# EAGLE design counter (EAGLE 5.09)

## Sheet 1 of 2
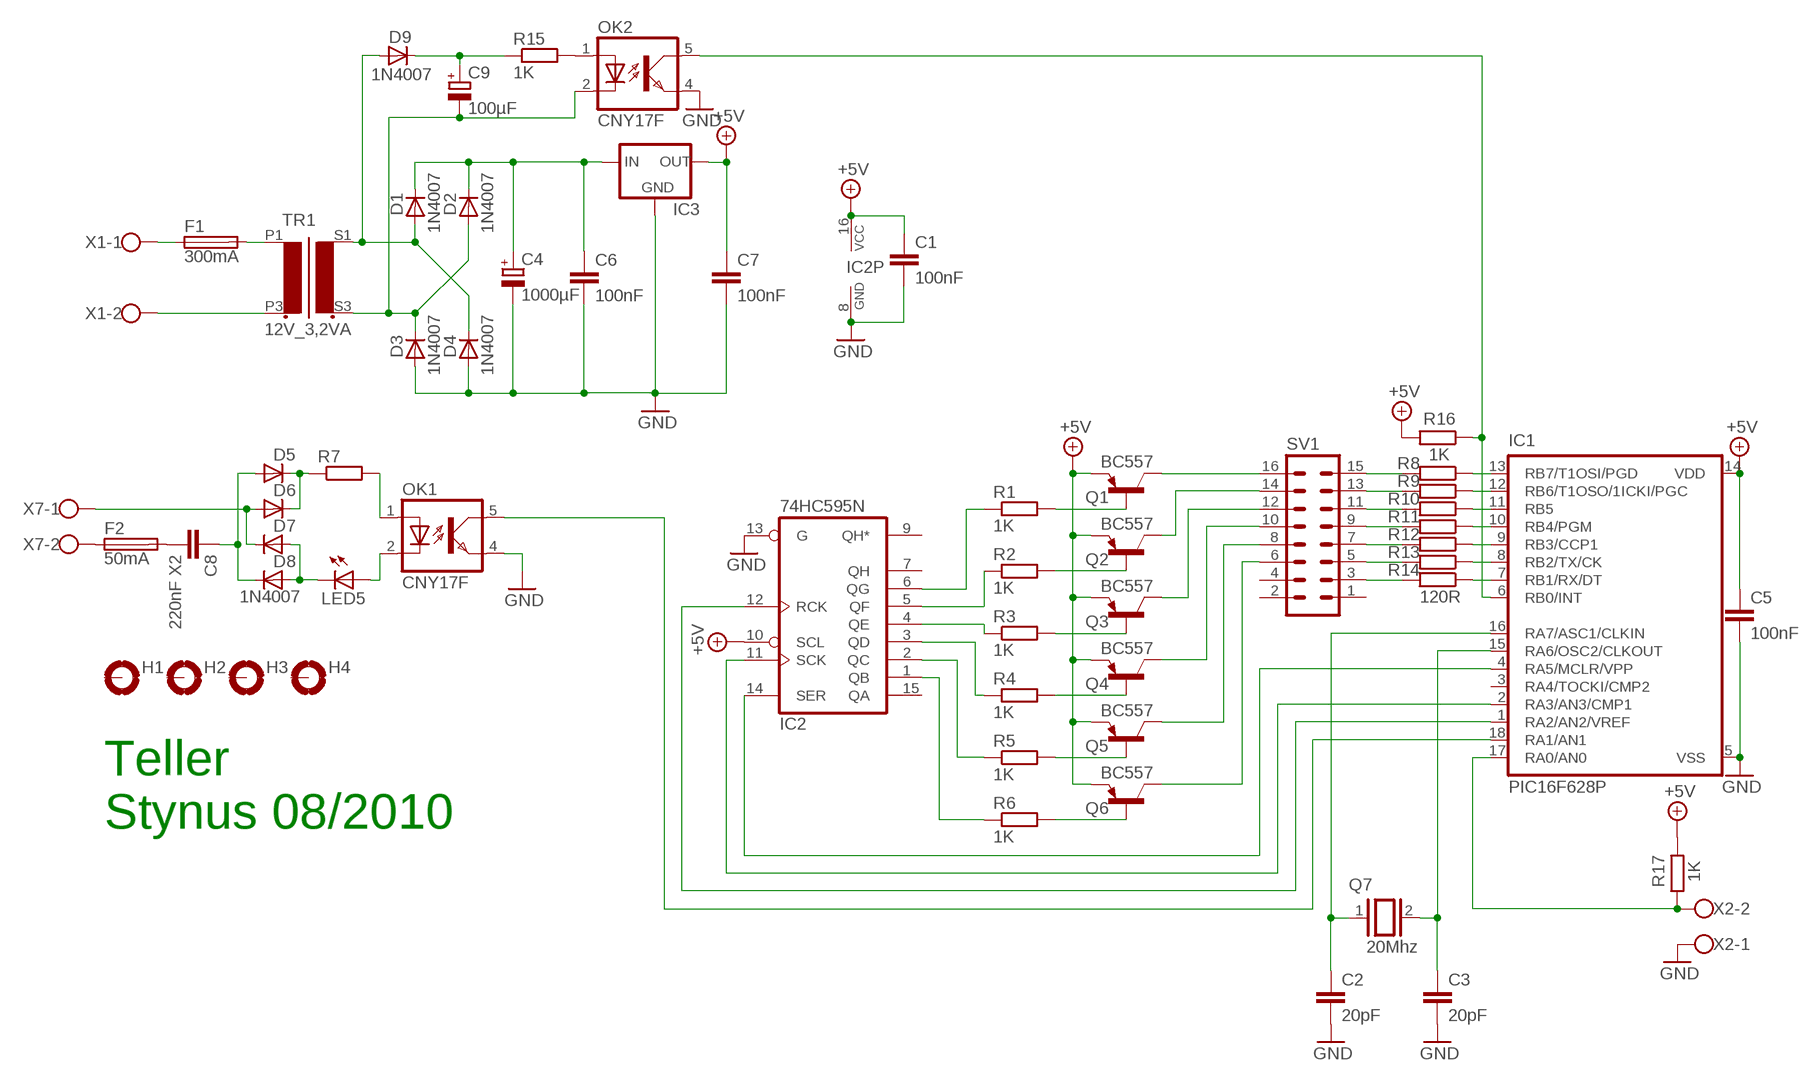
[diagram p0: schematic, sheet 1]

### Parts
C1  100nF  C-EU050-025X075  [C050-025X075]
C2  20pF  C-EU050-025X075  [C050-025X075]
C3  20pF  C-EU050-025X075  [C050-025X075]
C4  1000µF  CPOL-EUE5-13  [E5-13]
C5  100nF  C-EU050-025X075  [C050-025X075]
C6  100nF  C-EU050-025X075  [C050-025X075]
C7  100nF  C-EU050-025X075  [C050-025X075]
C8  220nF X2  C-EU150-091X182  [C150-091X182]
C9  100µF  CPOL-EUE5-10.5  [E5-10,5]
D1  1N4007  1N4004  [DO41-10]
D2  1N4007  1N4004  [DO41-10]
D3  1N4007  1N4004  [DO41-10]
D4  1N4007  1N4004  [DO41-10]
D5  1N4007  1N4004  [DO41-10]
D6  1N4007  1N4004  [DO41-10]
D7  1N4007  1N4004  [DO41-10]
D8  1N4007  1N4004  [DO41-10]
D9  1N4007  1N4004  [DO41-10]
F1  300mA  FUSESH22,5A  [SH22,5A]
F2  50mA  FUSESH22,5A  [SH22,5A]
H1  MOUNT-PAD-ROUND3.0  [3,0-PAD]
H2  MOUNT-PAD-ROUND3.0  [3,0-PAD]
H3  MOUNT-PAD-ROUND3.0  [3,0-PAD]
H4  MOUNT-PAD-ROUND3.0  [3,0-PAD]
IC1  PIC16F628P  [DIL18]
IC2  74HC595N  [DIL16]
IC3  78XXS  [78XXS]
LED5  LED5MM  [LED5MM]
OK1  CNY17F  [DIL06]
OK2  CNY17F  [DIL06]
Q1  BC557  BC557A  [TO92-EBC]
Q2  BC557  BC557A  [TO92-EBC]
Q3  BC557  BC557A  [TO92-EBC]
Q4  BC557  BC557A  [TO92-EBC]
Q5  BC557  BC557A  [TO92-EBC]
Q6  BC557  BC557A  [TO92-EBC]
Q7  20Mhz  XTAL/S  [QS]
R1  1K  R-EU_0204/7  [0204/7]
R2  1K  R-EU_0204/7  [0204/7]
R3  1K  R-EU_0204/7  [0204/7]
R4  1K  R-EU_0204/7  [0204/7]
R5  1K  R-EU_0204/7  [0204/7]
R6  1K  R-EU_0204/7  [0204/7]
R7  R-EU_0207/10  [0207/10]
R8  R-EU_0207/10  [0207/10]
R9  R-EU_0207/10  [0207/10]
R10  R-EU_0207/10  [0207/10]
R11  R-EU_0207/10  [0207/10]
R12  R-EU_0207/10  [0207/10]
R13  R-EU_0207/10  [0207/10]
R14  120R  R-EU_0207/10  [0207/10]
R15  1K  R-EU_0204/7  [0204/7]
R16  1K  R-EU_0207/10  [0207/10]
R17  1K  R-EU_0207/10  [0207/10]
SV1  MA08-2  [MA08-2]
TR1  12V_3,2VA  2V_3,2VA  [12V_3,2VA]
X1  W237-02P  [W237-132]
X2  W237-02P  [W237-132]
X7  W237-02P  [W237-132]

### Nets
+5V: C1.1 C5.1 C7.1 IC1.14(VDD) IC2.10(SCL) IC2.16(VCC) IC3.OUT Q1.E Q2.E Q3.E Q4.E Q5.E Q6.E R16.2 R17.1
GND: C1.2 C2.2 C3.2 C4.- C5.2 C6.2 C7.2 D3.A D4.A IC1.5(VSS) IC2.8(GND) IC2.13(G) IC3.GND OK1.4(EMIT) OK2.4(EMIT) X2.1
N$1: Q1.C SV1.16
N$2: Q2.C SV1.14
N$3: Q3.C SV1.12
N$4: Q4.C SV1.10
N$5: R8.2 SV1.15
N$6: R9.2 SV1.13
N$7: R10.2 SV1.11
N$8: Q5.C SV1.8
N$9: Q6.C SV1.6
N$10: Q1.B R1.2
N$11: Q2.B R2.2
N$12: Q3.B R3.2
N$13: Q4.B R4.2
N$14: IC1.13(RB7/T1OSI/PGD) R8.1
N$15: Q5.B R5.2
N$16: IC1.12(RB6/T1OSO/1ICKI/PGC) R9.1
N$17: Q6.B R6.2
N$18: IC2.6(QG) R1.1
N$19: IC2.5(QF) R2.1
N$20: IC1.11(RB5) R10.1
N$21: IC2.4(QE) R3.1
N$22: R11.2 SV1.9
N$23: IC1.10(RB4/PGM) R11.1
N$24: IC2.3(QD) R4.1
N$25: IC2.2(QC) R5.1
N$26: IC1.9(RB3/CCP1) R12.1
N$27: IC1.8(RB2/TX/CK) R13.1
N$28: R12.2 SV1.7
N$29: IC1.7(RB1/RX/DT) R14.1
N$30: C8.2 F2.2
N$31: R13.2 SV1.5
N$32: R14.2 SV1.3
N$33: D6.A D7.C X7.1
N$34: IC2.1(QB) R6.1
N$35: IC1.4(RA5/MCLR/VPP) IC2.14(SER)
N$36: IC1.2(RA3/AN3/CMP1) IC2.11(SCK)
N$37: IC1.1(RA2/AN2/VREF) IC2.12(RCK)
N$38: C3.1 IC1.15(RA6/OSC2/CLKOUT) Q7.2
N$39: C2.1 IC1.16(RA7/ASC1/CLKIN) Q7.1
N$40: D1.A D4.C D9.A TR1.S1
N$41: C9.- D2.A D3.C OK2.2(C) TR1.S3
N$42: C8.1 D5.A D8.C
N$43: F1.1 X1.1
N$44: TR1.P3 X1.2
N$45: F1.2 TR1.P1
N$46: C9.+ D9.C R15.1
N$47: D5.C D6.C R7.1
N$48: D7.A D8.A LED5.K(C)
N$49: OK1.1(A) R7.2
N$50: IC1.18(RA1/AN1) OK1.5(COL)
N$51: LED5.A OK1.2(C)
N$52: C4.+ C6.1 D1.C D2.C IC3.IN
N$53: OK2.1(A) R15.2
N$54: IC1.6(RB0/INT) OK2.5(COL) R16.1
N$55: IC1.17(RA0/AN0) R17.2 X2.2
N$56: F2.1 X7.2
Unconnected: H1.B3,0(MOUNT) H2.B3,0(MOUNT) H3.B3,0(MOUNT) H4.B3,0(MOUNT) IC1.3(RA4/TOCKI/CMP2) IC2.7(QH) IC2.9(QH*) IC2.15(QA) SV1.1 SV1.2 SV1.4

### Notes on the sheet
- Teller
- Stynus 08/2010

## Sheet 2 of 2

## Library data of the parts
C1-C3 C5-C8 = rcl:C-EU: CAPACITOR, European symbol
C4 C9 = rcl:CPOL-EU: POLARIZED CAPACITOR, European symbol
D1-D9 = diode:1N4004: DIODE
F1 F2 = fuse:FUSE: Fuse
H1-H4 = holes:MOUNT-PAD-ROUND: MOUNTING PAD, round
IC1 = microchip:PIC16*F62: FLASH-Based 8-Bit CMOS Microcontroller Source: http://ww1.microchip.com/downloads/en/DeviceDoc/40300C.pdf
IC2 = 74xx-eu:74*595: 8-bit SHIFT REGISTER, output latch
IC3 = v-reg:78XXS: VOLTAGE REGULATOR
LED5 = led:LED: LED
OK1 OK2 = optocoupler:CNY17F: SIEMENS OPTO COUPLER
Q1-Q6 = transistor-pnp:BC557*: PNP Transistror
Q7 = special:XTAL/S: CRYSTAL
R1-R17 = rcl:R-EU_: RESISTOR, European symbol
SV1 = con-lstb:MA08-2: PIN HEADER
TR1 = transfo_12V_3_2VA_Erea:2V_3,2VA
X1 X2 X7 = con-wago-508:W237-02P: WAGO SREW CLAMP

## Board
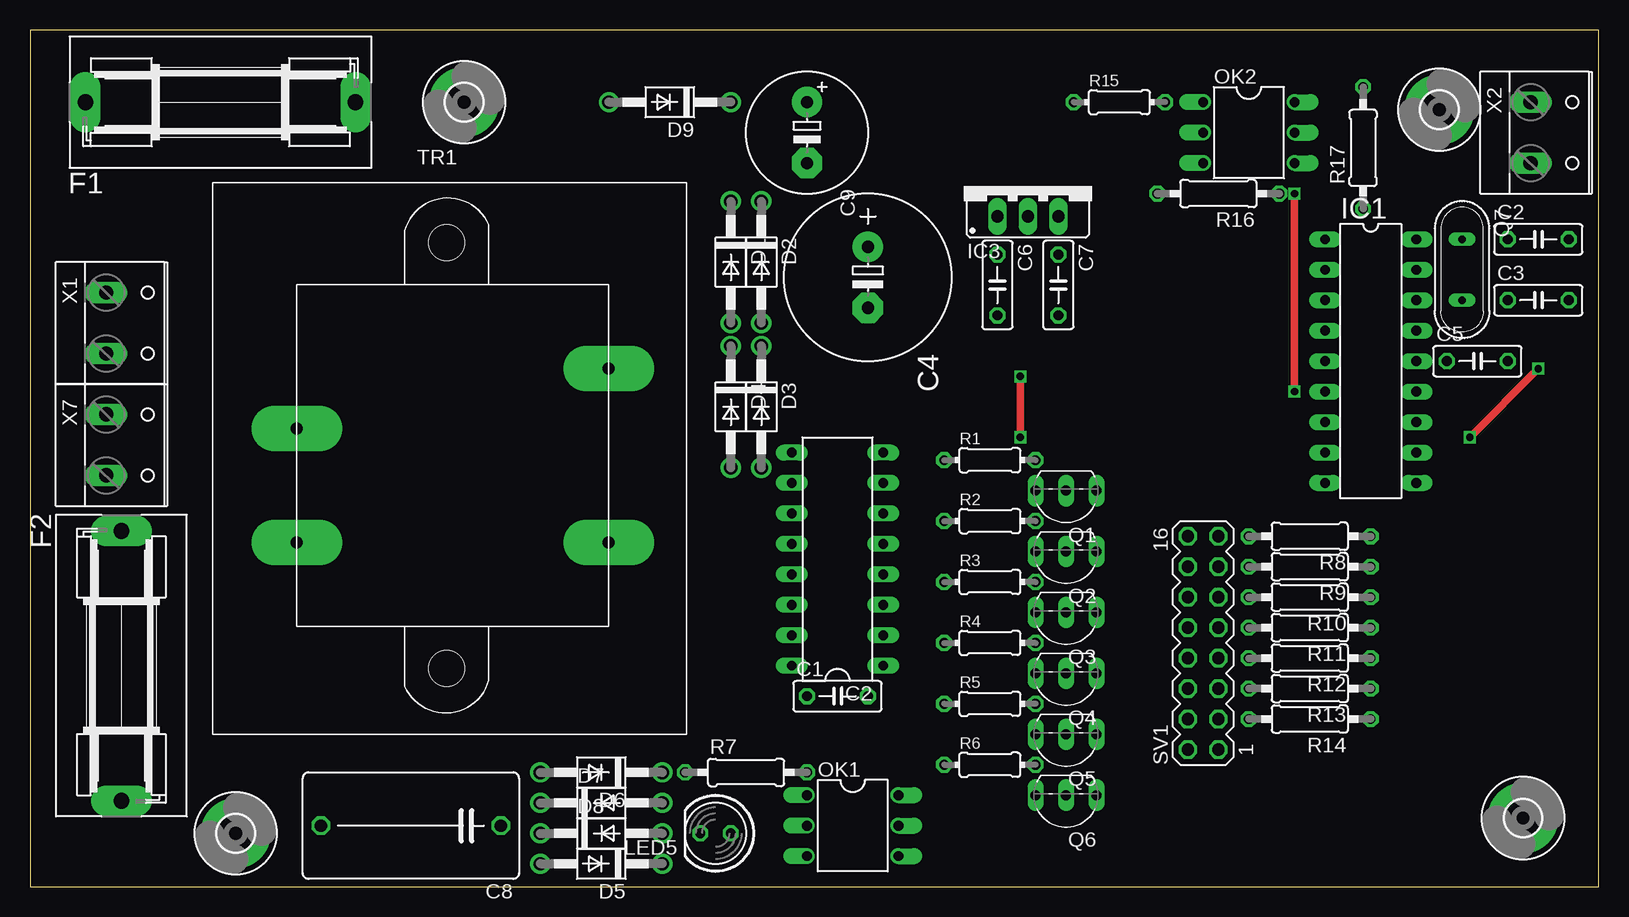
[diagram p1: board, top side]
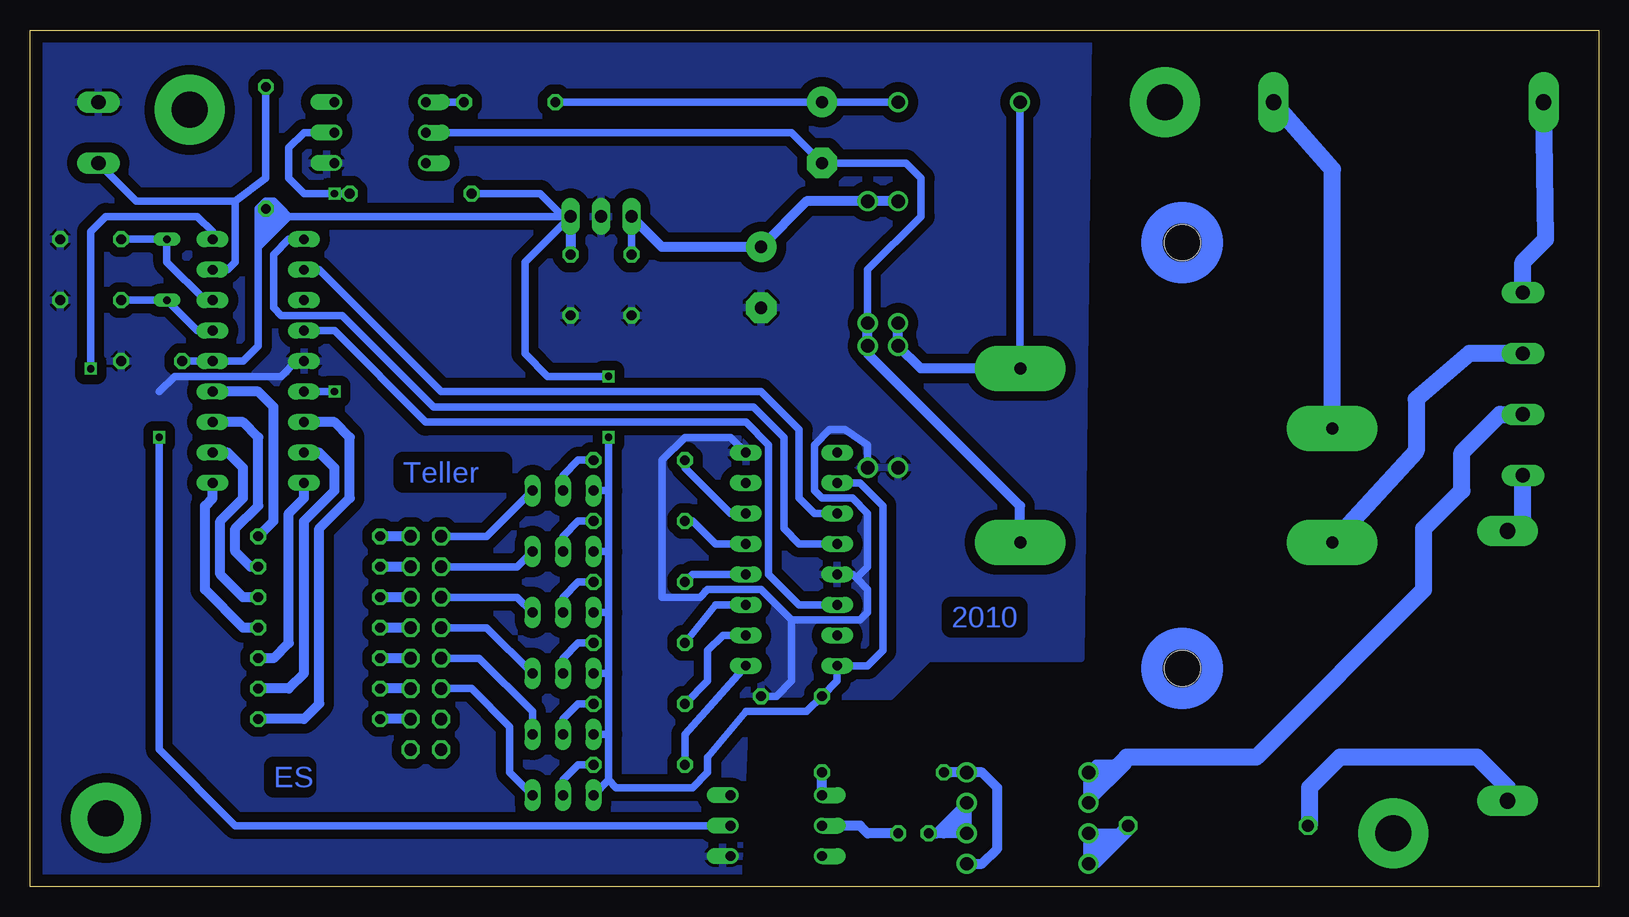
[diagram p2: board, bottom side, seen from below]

Size 130.79 x 71.42 mm. Coordinates in mm from the lower left corner, seen from the top.
Outline: 0,0 130.79,0 130.79,71.42 0,71.42 0,0
Copper layers (1*16): Top 0.035mm / dielectric 1.5mm / Bottom 0.035mm
Design rules "default": minimum track width 10mil, minimum drill 24mil, track to track 8mil, track to pad 8mil, pad to pad 8mil, via to via 8mil, smd to smd 8mil, copper to edge 40mil, drill to drill 8mil, minimum pad ring 10mil, minimum via ring 8mil, stop-mask expansion 4mil, vias tented up to drill 0mil, thermal gap 10mil

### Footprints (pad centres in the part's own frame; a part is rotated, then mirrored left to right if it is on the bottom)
C050-025X075 = drill 0.813 octagon: 1 -2.54,0; 2 2.54,0
E5-13 = drill 1.016 pad 2.54 round: + -2.54,0 | drill 1.016 pad 2.54 octagon: - 2.54,0
C150-091X182 = drill 1.016 octagon: 1 -7.493,0; 2 7.493,0
E5-10,5 = drill 1.016 pad 2.54 round: + -2.54,0 | drill 1.016 pad 2.54 octagon: - 2.54,0
DO41-10 = drill 1.118 round: A 5.08,0; C -5.08,0
SH22,5A = drill 1.321 pad 2.54 long: 1 -11.252,0; 2 11.252,0
3,0-PAD = drill 3 pad 5.842 round: B3,0 0,0
DIL18 = drill 0.813 long: 1 -10.16,-3.81; 2 -7.62,-3.81; 3 -5.08,-3.81; 4 -2.54,-3.81; 5 0,-3.81; 6 2.54,-3.81; 7 5.08,-3.81; 8 7.62,-3.81; 9 10.16,-3.81; 10 10.16,3.81; 11 7.62,3.81; 12 5.08,3.81; 13 2.54,3.81; 14 0,3.81; 15 -2.54,3.81; 16 -5.08,3.81; 17 -7.62,3.81; 18 -10.16,3.81
DIL16 = drill 0.813 long: 1 -8.89,-3.81; 2 -6.35,-3.81; 3 -3.81,-3.81; 4 -1.27,-3.81; 5 1.27,-3.81; 6 3.81,-3.81; 7 6.35,-3.81; 8 8.89,-3.81; 9 8.89,3.81; 10 6.35,3.81; 11 3.81,3.81; 12 1.27,3.81; 13 -1.27,3.81; 14 -3.81,3.81; 15 -6.35,3.81; 16 -8.89,3.81
78XXS = drill 1.016 long: GND 0,-2.54; IN -2.54,-2.54; OUT 2.54,-2.54
LED5MM = drill 0.813 octagon: A -1.27,0; K 1.27,0
DIL06 = drill 0.813 offset: 1 -2.54,-3.81; 2 0,-3.81; 3 2.54,-3.81; 4 2.54,3.81; 5 0,3.81; 6 -2.54,3.81
TO92-EBC = drill 0.813 long: B 0,-1.27; C -2.54,-1.27; E 2.54,-1.27
QS = drill 0.61 long: 1 -2.54,0; 2 2.54,0
0204/7 = drill 0.813 octagon: 1 -3.81,0; 2 3.81,0
0207/10 = drill 0.813 octagon: 1 -5.08,0; 2 5.08,0
MA08-2 = drill 1.016 octagon: 1 -8.89,-1.27; 2 -8.89,1.27; 3 -6.35,-1.27; 4 -6.35,1.27; 5 -3.81,-1.27; 6 -3.81,1.27; 7 -1.27,-1.27; 8 -1.27,1.27; 9 1.27,-1.27; 10 1.27,1.27; 11 3.81,-1.27; 12 3.81,1.27; 13 6.35,-1.27; 14 6.35,1.27; 15 8.89,-1.27; 16 8.89,1.27
12V_3,2VA = drill 1 pad 3.81 long: P1 7,25.5; P3 7,16; S1 33,30.5; S3 33,16 | hole 3: 19.5,5.5; 19.5,41
W237-132 = drill 1.194 long: 1 -2.54,-0.635; 2 2.54,-0.635

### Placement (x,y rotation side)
C1  67.31,15.88 0 top
C2  125.73,53.98 0 top
C3  125.73,48.9 0 top
C4  69.85,50.8 270 top
C5  120.65,43.81 0 top
C6  80.64,50.16 270 top
C7  85.72,50.16 270 top
C8  31.75,5.08 180 top
C9  64.77,62.87 270 top
D1  58.42,52.07 270 top
D2  60.96,52.07 270 top
D3  60.96,40.01 270 top
D4  58.42,40.01 270 top
D5  47.62,1.91 180 top
D6  47.62,9.53 180 top
D7  47.62,6.99 0 top
D8  47.62,4.45 0 top
D9  53.34,65.41 180 top
F1  15.88,65.41 0 top
F2  7.62,18.41 270 top
H1  17.14,4.45 0 top
H2  36.2,65.41 0 top
H3  124.46,5.71 0 top
H4  117.47,64.77 0 top
IC1  111.76,43.81 270 top
IC2  67.31,27.3 90 top
IC3  83.19,58.42 0 top
LED5  57.15,4.45 180 top
OK1  68.58,5.08 270 top
OK2  101.6,62.87 270 top
Q1  86.36,31.75 180 top
Q2  86.36,26.67 180 top
Q3  86.36,21.59 180 top
Q4  86.36,16.51 180 top
Q5  86.36,11.43 180 top
Q6  86.36,6.35 180 top
Q7  119.38,51.44 270 top
R1  80.01,35.56 0 top
R2  80.01,30.48 0 top
R3  80.01,25.4 0 top
R4  80.01,20.32 0 top
R5  80.01,15.24 0 top
R6  80.01,10.16 0 top
R7  59.69,9.53 0 top
R8  106.68,29.21 180 top
R9  106.68,26.67 180 top
R10  106.68,24.13 180 top
R11  106.68,21.59 180 top
R12  106.68,19.05 180 top
R13  106.68,16.51 180 top
R14  106.68,13.97 180 top
R15  90.81,65.41 0 top
R16  99.06,57.78 180 top
R17  111.12,61.59 90 top
SV1  97.79,20.32 90 top
TR1  15.24,12.7 0 top
X1  6.99,46.99 270 top
X2  125.73,62.87 270 top
X7  6.99,36.83 270 top

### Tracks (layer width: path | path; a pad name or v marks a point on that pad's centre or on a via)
+5V  (via drill 0.6)
  Top 0.61: v82.55,37.47 v82.55,42.55
  Bottom 0.61: IC2.10 61.59,33.66 59.69,31.75 59.69,19.68 60.96,18.41 IC2.16 63.5,17.14 C1.1 66.04,14.61 71.12,14.61 74.3,10.79 74.3,9.53 75.56,8.26 81.92,8.26 82.55,8.89 | 82.55,8.89 Q6.E | 82.55,8.89 82.55,12.7 | 82.55,12.7 82.55,17.78 | 82.55,17.78 82.55,22.86 | 82.55,22.86 82.55,27.94 | 82.55,27.94 82.55,33.02 | 82.55,27.94 Q2.E | 82.55,22.86 Q3.E | 82.55,17.78 Q4.E | 82.55,12.7 Q5.E | C5.1 IC1.14 113.03,43.81 111.76,45.09 111.76,53.34 | 109.22,55.88 111.76,53.34 | 85.72,55.24 86.36,55.88 | 82.55,33.02 Q1.E | 82.55,33.02 v82.55,37.47 | v82.55,42.55 87.63,42.55 89.53,44.45 89.53,52.07 IC3.OUT | R16.2 88.27,57.78 86.36,55.88 | 109.86,56.52 110.49,56.52 | 110.49,56.52 R17.1 111.76,55.88 | 109.22,55.88 109.86,56.52 | 111.76,55.88 111.76,55.24 | 111.76,53.98 111.76,54.61 | 111.76,53.34 111.76,53.98 | 111.76,53.98 109.86,55.88 110.49,56.52 | 110.49,56.52 110.49,55.88 111.76,54.61 | 111.76,54.61 111.76,55.24 | 111.76,55.24 111.12,55.88 | 86.36,55.88 109.22,55.88 | 109.86,56.52 110.49,57.15 111.12,57.15 111.76,56.52 111.76,55.88
  Bottom 0.813: C7.1 85.72,55.24 IC3.OUT
GND
  Bottom 0.61: IC2.8 72.39,37.47 76.2,37.47 78.11,35.56 78.11,24.13 74.93,24.13 74.3,24.77 69.85,24.77 67.31,22.23 | 67.31,22.23 61.59,22.23 60.96,22.86 60.96,24.77 61.91,25.72 | 61.91,25.72 62.23,26.04 IC2.13 | IC1.5 108.58,43.81 109.86,42.55 118.75,42.55 120.02,41.27 | C1.2 68.58,15.88 67.31,17.14 67.31,22.23 | D3.A 60.96,36.83 62.87,38.1 64.14,38.1 65.41,36.83 65.41,33.02 64.77,32.38 62.23,32.38 60.96,31.11 60.96,26.67 61.91,25.72
  pour Bottom (isolate 0.813): 43.18,19.05 55.88,19.05 59.05,15.88 71.12,15.88 71.75,0 130.18,0 130.18,71.12 42.55,71.12
N$1
  Bottom 0.61: SV1.16 92.71,29.21 Q1.C
N$2
  Bottom 0.61: SV1.14 90.17,26.67 Q2.C
N$3
  Bottom 0.61: SV1.12 90.17,24.13 Q3.C
N$4
  Bottom 0.61: SV1.10 92.71,21.59 Q4.C
N$5
  Bottom 0.813: SV1.15 R8.2
N$6
  Bottom 0.813: SV1.13 R9.2
N$7
  Bottom 0.813: SV1.11 R10.2
N$8
  Bottom 0.61: SV1.8 93.34,19.05 88.9,14.61 Q5.C
N$9
  Bottom 0.61: SV1.6 93.98,16.51 90.81,13.34 90.81,9.53 Q6.C
N$10
  Bottom 0.61: R1.2 85.09,35.56 86.36,34.29 Q1.B
N$11
  Bottom 0.61: Q2.B 86.36,29.21 85.09,30.48 R2.2
N$12
  Bottom 0.61: Q3.B 86.36,24.13 85.09,25.4 R3.2
N$13
  Bottom 0.61: Q4.B 86.36,19.05 85.09,20.32 R4.2
N$14
  Bottom 0.813: R8.1 110.49,30.48 110.49,40.01 111.76,41.27 IC1.13
N$15
  Bottom 0.61: Q5.B 86.36,13.97 85.09,15.24 R5.2
N$16
  Bottom 0.813: IC1.12 113.03,38.73 111.76,37.47 111.76,31.75 113.67,29.84 113.67,27.94 112.39,26.67 R9.1
N$17
  Bottom 0.61: Q6.B 86.36,8.89 85.09,10.16 R6.2
N$18
  Bottom 0.61: IC2.6 72.39,31.11 76.2,34.92 R1.1
N$19
  Bottom 0.61: IC2.5 73.66,28.57 75.56,30.48 R2.1
N$20
  Bottom 0.813: R10.1 113.03,24.13 114.94,26.04 114.94,30.48 113.03,32.38 113.03,34.92 114.3,36.2 IC1.11
N$21
  Bottom 0.61: IC2.4 75.56,26.04 R3.1
N$22
  Bottom 0.813: SV1.9 R11.2
N$23
  Bottom 0.813: IC1.10 115.57,32.38 116.2,31.75 116.2,24.77 113.03,21.59 R11.1
N$24
  Bottom 0.61: IC2.3 73.66,23.5 R4.1
N$25
  Bottom 0.61: IC2.2 73.03,20.95 74.3,19.68 74.3,17.14 R5.1
N$26
  Bottom 0.813: IC1.9 107.95,32.38 109.22,31.11 109.22,20.32 110.49,19.05 R12.1
N$27
  Bottom 0.813: R13.1 109.22,16.51 107.95,17.78 107.95,30.48 105.41,33.02 105.41,34.92 106.68,36.2 IC1.8
N$28
  Bottom 0.813: SV1.7 R12.2
N$29
  Bottom 0.813: IC1.7 105.41,38.73 104.14,37.47 104.14,32.38 106.68,29.84 106.68,15.24 107.95,13.97 R14.1
N$30
  Bottom 1.422: F2.2 7.62,8.26 10.16,10.79 21.59,10.79 24.13,8.26 24.13,5.21 C8.2
N$31
  Bottom 0.813: SV1.5 R13.2
N$32
  Bottom 0.813: SV1.3 R14.2
N$33
  Bottom 0.813: 40.01,10.16 40.64,10.16 | 40.64,10.16 41.27,10.16 | 41.27,10.16 41.91,10.16 D6.A 42.55,8.89 | 42.55,7.62 D7.C 39.37,10.16 40.01,10.16 | 42.55,7.62 40.64,9.53 40.01,10.16 | 42.55,7.62 42.55,8.89 | 42.55,8.89 41.27,10.16 | 40.64,10.16 41.91,8.89
  Bottom 1.422: X7.1 8.26,39.37 11.43,36.2 11.43,33.02 14.61,29.84 14.61,24.77 28.57,10.79 39.37,10.79 40.64,9.53
N$34
  Bottom 0.61: IC2.1 76.2,12.7 R6.1
N$35
  Bottom 0.61: IC2.14 66.67,23.5 69.22,26.04 69.22,36.83 71.12,38.73 97.79,38.73 105.41,46.35 IC1.4
N$36
  Bottom 0.61: IC2.11 65.41,31.11 66.67,32.38 66.67,38.1 69.85,41.27 96.52,41.27 106.68,51.44 IC1.2 108.58,51.44
N$37
  Bottom 0.61: IC2.12 66.67,28.57 67.94,29.84 67.94,37.47 70.48,40.01 97.16,40.01 104.78,47.62 109.86,47.62 110.49,48.26 110.49,52.7 109.22,53.98 IC1.1
N$38
  Bottom 0.61: C3.1 Q7.2 116.84,46.35 IC1.15
N$39
  Bottom 0.61: C2.1 Q7.1 119.38,52.07 116.2,48.9 IC1.16
N$40
  Bottom 0.61: D9.A 48.26,43.22 TR1.S1
  Bottom 0.813: TR1.S1 56.53,43.2 D4.C D1.A
N$41
  Bottom 0.61: OK2.2 67.31,62.87 C9.- 57.78,60.33 56.52,59.05 56.52,55.88 60.96,51.44 D2.A
  Bottom 0.813: D2.A D3.C 60.96,44.45 48.26,31.75 48.26,28.72 TR1.S3
N$42
  Bottom 0.813: C8.1 39.24,4.57 40.64,3.17 | 41.27,3.17 40.64,3.17 | 42.55,3.17 41.27,3.17 | 42.55,3.17 D8.C | D5.A 42.55,3.17 | 41.91,3.81 D8.C | 41.27,3.17 41.91,3.81 | D5.A 41.27,3.17 | D5.A 41.91,1.91 40.64,3.17 | D8.C 40.01,4.45 | 40.01,4.45 39.37,5.08 | 41.91,3.81 40.64,3.81 40.01,4.45
N$43
  Bottom 1.422: X1.1 6.35,52.07 4.45,53.98 F1.1
N$44
  Bottom 1.422: X1.2 10.79,44.45 15.24,40.64 15.24,36.34 TR1.P3
N$45
  Bottom 1.422: F1.2 22.23,59.8 TR1.P1
N$46
  Bottom 0.61: R15.1 C9.+ D9.C
N$47
  Bottom 0.813: R7.1 D6.C 51.44,9.53 50.16,8.26 50.16,3.17 51.44,1.91 D5.C
N$48
  Bottom 0.813: 54.61,4.45 D8.A D7.A 55.24,4.45 | 55.24,4.45 LED5.K | 54.61,4.45 55.24,4.45 | 54.61,4.45 53.34,5.71 53.34,5.08
N$49
  Bottom 0.813: OK1.1 R7.2
N$50  (via drill 0.6)
  Top 0.61: v120.02,37.47 v125.73,43.18
  Bottom 0.61: OK1.5 113.67,5.08 120.02,11.43 v120.02,37.47 | v125.73,43.18 125.73,54.61 124.46,55.88 116.84,55.88 115.57,54.61 IC1.18
N$51
  Bottom 0.813: LED5.A 60.96,4.45 61.59,5.08 OK1.2
N$52
  Bottom 0.61: IC3.IN C6.1
  Bottom 0.813: D1.C D2.C 66.04,57.15 C4.+ 78.11,53.34 IC3.IN
N$53
  Bottom 0.61: R15.2 OK2.1
N$54  (via drill 0.6)
  Top 0.61: v105.41,41.27 v105.41,57.78
  Bottom 0.61: v105.41,41.27 IC1.6 | OK2.5 107.95,62.87 109.22,61.59 109.22,59.05 107.95,57.78 v105.41,57.78 R16.1
N$55
  Bottom 0.61: IC1.17 114.3,51.44 113.67,52.07 113.67,57.15 | 113.67,57.15 111.12,59.05 R17.2 | 113.67,57.15 121.92,57.15 X2.2
N$56
  Bottom 1.422: F2.1 7.16,29.67 6.35,30.48 X7.2

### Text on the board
Bottom: Teller | 2010 | ES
